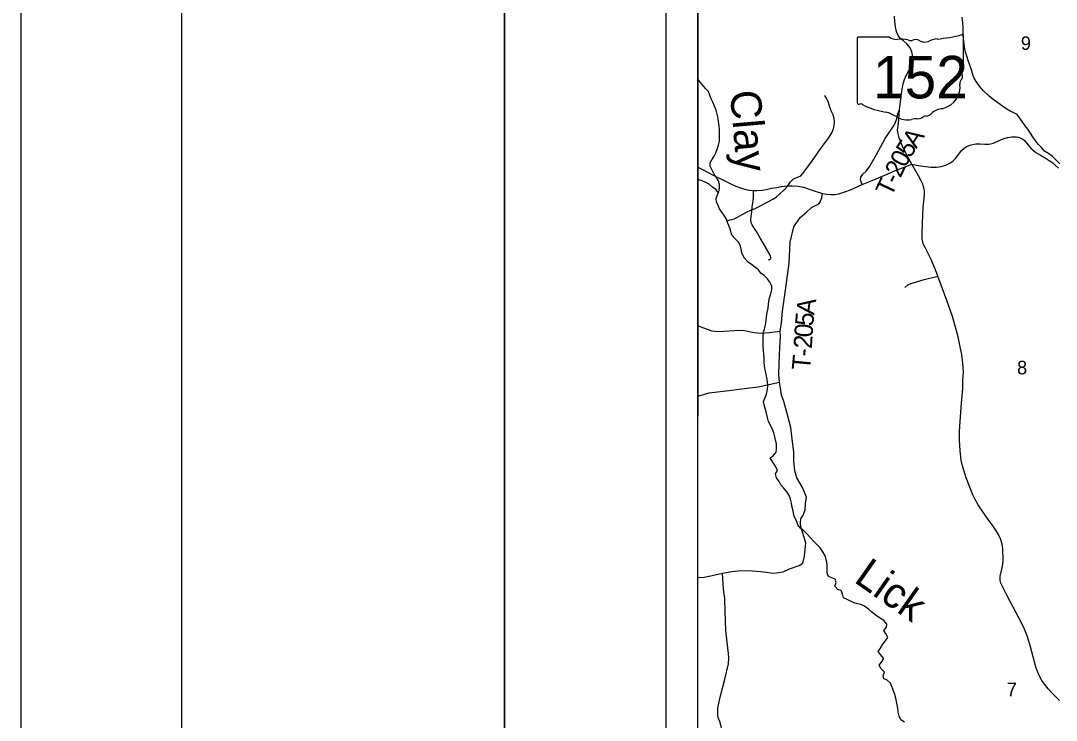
# Model space of a CAD drawing. Extents: x 0 to 34, y 0 to 22.
# Drawn here: x 0 to 3.211, y 16.097 to 18.266 of the extents above; entities that cross this region are included whole.
import ezdxf

# ---------------------------------------------------------------- set-up
doc = ezdxf.new("R2010")
doc.units = 0
for name, color, linetype in [('GM_X_Corporation', 7, 'Continuous'), ('GM_X_Minor_River', 7, 'Continuous'), ('GM_X_Minor_River_Text', 7, 'Continuous'), ('GM_X_Section_Text', 7, 'Continuous'), ('GM_X_State_Location', 7, 'Continuous'), ('GM_X_State_Route', 7, 'Continuous'), ('GM_X_State_Shield', 7, 'Continuous'), ('GM_X_Township_Road', 7, 'Continuous'), ('GM_X_Township_Road_Text', 7, 'Continuous'), ('SH_Border', 7, 'Continuous'), ('SH_Cut_Line', 7, 'Continuous'), ('SH_Data', 7, 'Continuous')]:
    doc.layers.add(name, color=color, linetype=linetype)

msp = doc.modelspace()

# ---------------------------------------------------------------- linework, layer by layer
at = {"layer": 'GM_X_Corporation'}
msp.add_lwpolyline([(4.6083, 17.0396), (4.6111, 17.2406), (4.6176, 17.7005), (4.6283, 18.459), (4.6386, 19.1863), (4.6534, 20.2382), (4.6627, 20.9), (2.1, 20.9), (2.1, 17.0396)], dxfattribs=at)
at = {"layer": 'GM_X_Minor_River'}
for points in [[(3.2225, 17.822), (3.2087, 17.8363), (3.1983, 17.8457), (3.1875, 17.8543), (3.1744, 17.8621), (3.1652, 17.8726), (3.1551, 17.8831), (3.1455, 17.8955), (3.1389, 17.9057), (3.1315, 17.9174), (3.1229, 17.9294), (3.1148, 17.94), (3.0978, 17.9641), (3.0896, 17.975), (3.0796, 17.9806), (3.0682, 17.9857), (3.0578, 17.9924), (3.0447, 18.0014), (3.0298, 18.0111), (3.0155, 18.0223), (3.0029, 18.0324), (2.9855, 18.0492), (2.9735, 18.0631), (2.9631, 18.0775), (2.9557, 18.0899), (2.9509, 18.1028), (2.9481, 18.1138), (2.939, 18.1399), (2.9335, 18.1562), (2.9299, 18.169), (2.927, 18.1846), (2.9241, 18.2032), (2.9228, 18.2195), (2.9224, 18.2454), (2.9215, 18.2598), (2.9197, 18.2769)], [(2.244, 17.5295), (2.2374, 17.5435), (2.2317, 17.5674), (2.2266, 17.5787), (2.2151, 17.5896), (2.2054, 17.6013), (2.1998, 17.6202), (2.1959, 17.6308), (2.1919, 17.6406), (2.1884, 17.6512), (2.1818, 17.6626), (2.1736, 17.6723), (2.167, 17.6833), (2.1623, 17.6935), (2.1572, 17.7048), (2.1563, 17.7151), (2.1611, 17.7265), (2.1652, 17.7361), (2.1673, 17.7456), (2.1664, 17.7586), (2.164, 17.7696), (2.1577, 17.7805), (2.1504, 17.7903), (2.1437, 17.8031), (2.1382, 17.8152), (2.1381, 17.8251), (2.1429, 17.8347), (2.1504, 17.8462), (2.156, 17.8569), (2.16, 17.8676), (2.1636, 17.8798), (2.1665, 17.8928), (2.1671, 17.9069), (2.1673, 17.9175), (2.1668, 17.9286), (2.1655, 17.9411), (2.1642, 17.9525), (2.1625, 17.9635), (2.1597, 17.9764), (2.1561, 17.9889), (2.151, 18.0014), (2.1459, 18.0135), (2.1412, 18.0237), (2.1368, 18.035), (2.1329, 18.0468), (2.1236, 18.0565), (2.1128, 18.0682), (2.1031, 18.0806), (2.1, 18.0867)], [(2.1902, 17.6457), (2.1998, 17.6491), (2.2127, 17.652), (2.2225, 17.6566), (2.2376, 17.6656), (2.2505, 17.6722), (2.2645, 17.6789), (2.2773, 17.684), (2.2902, 17.6903), (2.3012, 17.6965), (2.311, 17.702), (2.3212, 17.707), (2.3321, 17.7129), (2.3423, 17.7191), (2.3555, 17.7307), (2.366, 17.7404), (2.3784, 17.7546), (2.3855, 17.7653), (2.396, 17.7761), (2.4069, 17.7805), (2.4191, 17.7852), (2.4288, 17.7963), (2.437, 17.8075), (2.4467, 17.8213), (2.4561, 17.8347), (2.4643, 17.8466), (2.4729, 17.8589), (2.4916, 17.8843), (2.4998, 17.895), (2.5069, 17.905), (2.5155, 17.9181), (2.5206, 17.9307), (2.5224, 17.9414), (2.523, 17.952), (2.5221, 17.9627), (2.5189, 17.9744), (2.5134, 17.9869), (2.5075, 18.0016), (2.5047, 18.0122), (2.4996, 18.0244), (2.493, 18.0341)], [(2.1637, 17.7327), (2.1556, 17.7424), (2.1456, 17.7503), (2.1348, 17.7589), (2.1245, 17.7648), (2.1134, 17.7696), (2.1027, 17.7729), (2.1, 17.7735)], [(2.6292, 16.4421), (2.6169, 16.4511), (2.6051, 16.4566), (2.5948, 16.4584), (2.5844, 16.4616), (2.5733, 16.4668), (2.563, 16.472), (2.5515, 16.4764), (2.5479, 16.4893), (2.544, 16.4991), (2.5337, 16.5027), (2.5244, 16.5129), (2.5284, 16.5243), (2.5256, 16.535), (2.5153, 16.539), (2.5046, 16.5426), (2.501, 16.5532), (2.5005, 16.5665), (2.5011, 16.5764), (2.4998, 16.5874), (2.4942, 16.6071), (2.4876, 16.6196), (2.479, 16.6316), (2.469, 16.6418), (2.4586, 16.6523), (2.4486, 16.6632), (2.4389, 16.6744), (2.4285, 16.6846), (2.4185, 16.6924), (2.41, 16.7033), (2.4068, 16.7132), (2.4017, 16.723), (2.3978, 16.7336), (2.3949, 16.7464), (2.3925, 16.7571), (2.3901, 16.77), (2.3872, 16.7828), (2.3829, 16.7946), (2.3766, 16.8047), (2.3651, 16.8175), (2.3573, 16.8277), (2.3515, 16.8375), (2.3433, 16.8484), (2.3409, 16.8609), (2.3464, 16.872), (2.3414, 16.883), (2.332, 16.898), (2.3235, 16.9109), (2.3333, 16.9175), (2.3423, 16.9282), (2.3433, 16.9385), (2.3434, 16.9545), (2.341, 16.9658), (2.3382, 16.9765), (2.335, 16.9882), (2.3314, 16.9992), (2.3256, 17.0097), (2.3193, 17.0237), (2.3153, 17.0362), (2.3117, 17.0533), (2.3089, 17.0639), (2.3053, 17.0752), (2.3032, 17.0855), (2.308, 17.0977), (2.3128, 17.1084), (2.3161, 17.1225), (2.3163, 17.1358), (2.3149, 17.1541), (2.3112, 17.1708), (2.3088, 17.1836), (2.3063, 17.1958), (2.305, 17.2072), (2.3049, 17.2197), (2.304, 17.2315), (2.3034, 17.244), (2.3025, 17.2554), (2.3019, 17.2672), (2.3018, 17.2767), (2.3021, 17.2866), (2.3038, 17.3003), (2.3063, 17.3102), (2.31, 17.3232), (2.3117, 17.3373), (2.313, 17.348), (2.3148, 17.3617), (2.3173, 17.3746), (2.3186, 17.3864), (2.32, 17.3967), (2.3221, 17.4074), (2.3262, 17.4196), (2.3294, 17.4318), (2.3289, 17.4429), (2.3234, 17.4557), (2.3157, 17.4655), (2.3049, 17.4764), (2.2949, 17.4831), (2.2883, 17.4936), (2.2756, 17.5034), (2.2656, 17.5101), (2.2556, 17.5179), (2.244, 17.5295)], [(2.7401, 16.0912), (2.7294, 16.0983), (2.7239, 16.1096), (2.7214, 16.1221), (2.7194, 16.1343), (2.7181, 16.1453), (2.716, 16.1555), (2.7136, 16.1661), (2.7104, 16.1767), (2.7017, 16.2017), (2.6974, 16.2127), (2.6862, 16.2228), (2.6763, 16.2257), (2.6742, 16.2359), (2.6783, 16.2462), (2.6686, 16.2567), (2.6616, 16.2677), (2.6695, 16.2777), (2.6766, 16.2888), (2.6661, 16.3008), (2.6592, 16.311), (2.6662, 16.321), (2.6737, 16.3328), (2.6815, 16.3432), (2.689, 16.354), (2.6836, 16.3638), (2.6762, 16.3751), (2.6844, 16.3862), (2.6854, 16.3957), (2.6765, 16.4066), (2.6646, 16.4141), (2.6539, 16.4211), (2.6393, 16.4327), (2.6292, 16.4421)]]:
    msp.add_lwpolyline(points, dxfattribs=at)
at = {"layer": 'GM_X_State_Route'}
for points in [[(2.7636, 17.8211), (2.7507, 17.8433), (2.734, 17.8767), (2.7288, 17.89), (2.7241, 17.9028), (2.7204, 17.9157), (2.7189, 17.9263), (2.722, 17.9477), (2.7252, 17.9894), (2.7269, 18.0072), (2.7309, 18.0393), (2.7329, 18.0538), (2.7362, 18.0707), (2.7406, 18.0839), (2.7458, 18.0965), (2.7538, 18.1118), (2.76, 18.1247), (2.7631, 18.1364), (2.7652, 18.1509), (2.7649, 18.1605), (2.7634, 18.1692), (2.7609, 18.175), (2.7576, 18.182), (2.7485, 18.1938), (2.7375, 18.2037), (2.7286, 18.2108), (2.7223, 18.2178), (2.7166, 18.2292), (2.7133, 18.2396), (2.7104, 18.2638), (2.7096, 18.2803)], [(2.7636, 17.8211), (2.7766, 17.8183), (2.8057, 17.8139), (2.8226, 17.812), (2.8401, 17.8116), (2.8538, 17.814), (2.8685, 17.8188), (2.8807, 17.8244), (2.8909, 17.831), (2.8984, 17.8388), (2.9085, 17.8528), (2.9168, 17.8638), (2.9255, 17.8713), (2.9332, 17.8762), (2.9473, 17.881), (2.9615, 17.8843), (2.9756, 17.8849), (2.9896, 17.8838), (3.001, 17.8835), (3.0073, 17.8841), (3.0161, 17.8869), (3.0324, 17.894), (3.0414, 17.8978), (3.0493, 17.9005), (3.0611, 17.9037), (3.0729, 17.9058), (3.0816, 17.9062), (3.0883, 17.9058), (3.0943, 17.9046), (3.1011, 17.9021), (3.1074, 17.8987), (3.1123, 17.8944), (3.1168, 17.8892), (3.1323, 17.8714), (3.1396, 17.8645), (3.1478, 17.8579), (3.1622, 17.8491), (3.1795, 17.8387), (3.1893, 17.8331), (3.2003, 17.8254), (3.2091, 17.8174), (3.2179, 17.8086)], [(2.1, 17.8119), (2.1139, 17.8049), (2.1448, 17.7886), (2.1792, 17.7716), (2.2025, 17.7603), (2.2176, 17.7535), (2.2321, 17.748), (2.2447, 17.7442), (2.2601, 17.7409), (2.2722, 17.7397), (2.2831, 17.7396), (2.3001, 17.7409), (2.3113, 17.7431), (2.3285, 17.7466), (2.3443, 17.7495), (2.3595, 17.7521), (2.3773, 17.7539), (2.3924, 17.7546), (2.4107, 17.7534), (2.4271, 17.7497), (2.4454, 17.7442), (2.4639, 17.7379), (2.4862, 17.73)], [(2.6089, 17.7583), (2.625, 17.765), (2.6406, 17.7707), (2.6791, 17.7873), (2.7152, 17.8028), (2.7391, 17.8125), (2.7636, 17.8211)], [(3.0685, 16.4656), (3.0546, 16.4913), (3.045, 16.5101), (3.0393, 16.5226), (3.0374, 16.5309), (3.0368, 16.5445), (3.042, 16.5655), (3.0457, 16.5814), (3.0467, 16.595), (3.0451, 16.6283), (3.0433, 16.6434), (3.0382, 16.6599), (3.0317, 16.6735), (3.0239, 16.6864), (3.0186, 16.6937), (3.0129, 16.7025), (3.0022, 16.7171), (2.9867, 16.7391), (2.9692, 16.765), (2.96, 16.7815), (2.9525, 16.7966), (2.9315, 16.8494), (2.9203, 16.8866), (2.9163, 16.9038), (2.9127, 16.9323), (2.9109, 16.9668), (2.9106, 16.9922), (2.9129, 17.0234), (2.9177, 17.0799), (2.9209, 17.126), (2.9215, 17.1513), (2.9236, 17.1766), (2.9218, 17.2045), (2.918, 17.2318), (2.9127, 17.2551), (2.9071, 17.2862), (2.9007, 17.3089), (2.8889, 17.3495), (2.8719, 17.3992), (2.8547, 17.4462), (2.8437, 17.4743), (2.837, 17.4937), (2.8275, 17.5158), (2.8229, 17.5255), (2.8177, 17.5365), (2.8114, 17.5489), (2.8052, 17.5607), (2.7993, 17.5727), (2.7966, 17.5822), (2.795, 17.592), (2.7948, 17.6053), (2.7964, 17.638), (2.7988, 17.6867), (2.8021, 17.7268), (2.8021, 17.739), (2.8008, 17.748), (2.7985, 17.7557), (2.7969, 17.7597), (2.7921, 17.7697), (2.7836, 17.7852), (2.7636, 17.8211)], [(2.4862, 17.73), (2.4985, 17.7281), (2.5118, 17.7271), (2.5244, 17.7276), (2.5372, 17.7297), (2.555, 17.7352), (2.5728, 17.742), (2.6089, 17.7583)], [(3.2208, 16.1586), (3.1981, 16.1808), (3.1864, 16.195), (3.1762, 16.2078), (3.1666, 16.221), (3.1577, 16.2362), (3.1489, 16.2589), (3.1395, 16.294), (3.1311, 16.3249), (3.1261, 16.3421), (3.1206, 16.3586), (3.113, 16.3801), (3.1039, 16.3976), (3.0767, 16.4505), (3.0685, 16.4656)]]:
    msp.add_lwpolyline(points, dxfattribs=at)
at = {"layer": 'GM_X_State_Shield'}
for p, q in [((2.5938, 18.2114), (2.5938, 18.0112)), ((2.6936, 18.2148), (2.5971, 18.2148)), ((2.9234, 18.1151), (2.9234, 18.2198)), ((2.9234, 18.1151), (2.9234, 18.1151))]:
    msp.add_line(p, q, dxfattribs=at)
for centre, major_axis, start_param, end_param in [((2.5976, 18.2118), (0.00382, 0), 1.712693, 3.28349), ((2.7166, 18.238), (0.037, 0), 4.042523, 4.731795), ((2.7289, 18.1024), (0.133, 0), 1.404758, 1.657858), ((2.7747, 18.1897), (0.0222, 0), 0.950623, 2.079405), ((2.8506, 18.1537), (0.0703, 0), 1.699011, 2.107814), ((2.806, 18.4876), (0.3495, 0), 4.814394, 5.042369), ((2.9198, 18.2202), (0.00367, 0), 6.141152, 7.989035), ((2.7591, 18.2128), (0.0107, 0), 3.836095, 5.185415), ((2.8034, 18.2214), (0.0267, 0), 4.081561, 5.145723), ((2.9226, 18.1074), (0.00568, 0), 1.883978, 3.671073), ((2.9195, 18.1147), (0.00393, 0), 5.05454, 6.418171), ((2.9366, 18.0713), (0.0248, 0), 2.387724, 3.262537), ((2.8865, 18.0942), (0.0341, 0), 5.934695, 6.695948), ((2.8256, 18.0579), (0.0874, 0), 5.101752, 6.440018), ((2.5976, 18.0108), (0.00385, 0), 3.00124, 4.508301), ((2.5982, 18.0313), (0.0294, 0), 4.665946, 4.897461), ((2.6042, 17.9997), (0.0106, 0), 0.519207, 1.627899), ((2.7381, 18.1795), (0.2524, 0), 4.195997, 4.488961), ((2.8625, 17.9551), (0.0479, 0), 1.647645, 2.488434), ((2.6628, 17.9213), (0.079, 0), 0.823519, 1.323587), ((2.7482, 17.9987), (0.0501, 0), 4.026481, 4.996735), ((2.7772, 17.9295), (0.0412, 0), 1.495662, 1.94098), ((2.7809, 17.9837), (0.0267, 0), 4.691044, 5.507374), ((2.805, 17.9643), (0.00752, 0), 1.147584, 2.315152), ((2.8018, 17.9918), (0.0282, 0), 4.937069, 5.64225)]:
    msp.add_ellipse(centre, major_axis=major_axis, ratio=0.8, start_param=start_param, end_param=end_param, dxfattribs=at)
at = {"layer": 'GM_X_Township_Road'}
for points in [[(2.6089, 17.7583), (2.6042, 17.7718), (2.6052, 17.7814), (2.6117, 17.7906), (2.6217, 17.8002), (2.6333, 17.8152), (2.6541, 17.8514), (2.6804, 17.9014), (2.7083, 17.942), (2.7131, 17.9512), (2.7164, 17.9622), (2.7184, 17.9726), (2.7216, 17.9834), (2.7252, 17.9894)], [(2.4862, 17.73), (2.4985, 17.7281), (2.5118, 17.7271), (2.5244, 17.7276), (2.5372, 17.7297), (2.555, 17.7352), (2.5728, 17.742), (2.6089, 17.7583)], [(2.3186, 17.5249), (2.3207, 17.5256), (2.3231, 17.5262), (2.3246, 17.5278), (2.3258, 17.5297), (2.3262, 17.5321), (2.3253, 17.5358), (2.3228, 17.5412), (2.3122, 17.5591), (2.294, 17.5914), (2.2811, 17.6127), (2.2771, 17.619), (2.2732, 17.6254), (2.2686, 17.633), (2.2665, 17.6373), (2.265, 17.6417), (2.2644, 17.645), (2.2641, 17.6498), (2.2647, 17.6576), (2.2667, 17.6744), (2.2686, 17.6897), (2.2702, 17.7002), (2.271, 17.7083), (2.2719, 17.7159), (2.2723, 17.7249), (2.2722, 17.7397)], [(2.3528, 17.146), (2.3507, 17.1679), (2.3518, 17.204), (2.3544, 17.2534), (2.3558, 17.2876), (2.3551, 17.3034), (2.3592, 17.3292), (2.362, 17.3655), (2.3715, 17.4312), (2.3833, 17.5146), (2.3857, 17.5792), (2.3972, 17.6273), (2.4174, 17.6558), (2.4364, 17.6729), (2.4521, 17.6869), (2.4603, 17.6909), (2.4744, 17.6982), (2.4786, 17.7049), (2.484, 17.7169), (2.4862, 17.73)], [(2.7417, 17.4392), (2.7504, 17.4474), (2.7647, 17.4528), (2.8013, 17.4637), (2.8437, 17.4743)], [(2.1, 17.3217), (2.1141, 17.3149), (2.1291, 17.3098), (2.1436, 17.3048), (2.1642, 17.3023), (2.2292, 17.3069), (2.2444, 17.3058), (2.2746, 17.2997), (2.2953, 17.2976), (2.3205, 17.2995), (2.3551, 17.3034)], [(2.1, 17.1024), (2.1348, 17.1128), (2.2039, 17.1207)], [(2.1765, 16.5529), (2.2055, 16.5581), (2.2353, 16.5615), (2.2685, 16.5601), (2.2953, 16.5587), (2.3349, 16.5532), (2.3648, 16.5575), (2.3838, 16.5664), (2.4139, 16.5776), (2.4251, 16.5843), (2.4302, 16.6062), (2.4327, 16.6275), (2.4343, 16.6464), (2.4307, 16.6606), (2.4231, 16.6836), (2.419, 16.6963), (2.418, 16.709), (2.4188, 16.7214), (2.4258, 16.7329), (2.4322, 16.7501), (2.4337, 16.7695), (2.4368, 16.789), (2.4246, 16.8185), (2.4068, 16.8491), (2.4001, 16.871), (2.3976, 16.9005), (2.3971, 16.9295), (2.3925, 16.9693), (2.3879, 17.0054), (2.3777, 17.0446), (2.366, 17.0859), (2.3594, 17.1052), (2.3558, 17.1266), (2.3528, 17.146)], [(2.2039, 17.1207), (2.2449, 17.1254), (2.2863, 17.1314), (2.3528, 17.146)], [(2.1, 16.5414), (2.103, 16.5404), (2.1195, 16.5412), (2.135, 16.544), (2.1765, 16.5529)], [(2.2547, 15.9306), (2.2109, 15.9927), (2.2009, 16.0061), (2.1892, 16.0253), (2.1777, 16.0582), (2.1677, 16.0933), (2.163, 16.1054), (2.1612, 16.1152), (2.1612, 16.1267), (2.1621, 16.1357), (2.1695, 16.1735), (2.1833, 16.2247), (2.1943, 16.2722), (2.1958, 16.2895), (2.195, 16.3043), (2.1869, 16.3755), (2.1842, 16.4343), (2.1837, 16.4743), (2.1793, 16.5039), (2.1765, 16.5529)]]:
    msp.add_lwpolyline(points, dxfattribs=at)
at = {"layer": 'SH_Border'}
for points in [[(0.5, 21.5), (1.5, 21.5), (1.5, 0.5), (0.5, 0.5)], [(1.5, 21.5), (33.5, 21.5), (33.5, 0.5), (1.5, 0.5)]]:
    msp.add_lwpolyline(points, close=True, dxfattribs=at)
at = {"layer": 'SH_Cut_Line'}
msp.add_lwpolyline([(0, 0), (34, 0), (34, 22), (0, 22)], close=True, dxfattribs=at)
at = {"layer": 'SH_Data'}
msp.add_line((2, 21), (2, 14), dxfattribs=at)
msp.add_lwpolyline([(2.1, 20.9), (8.9, 20.9), (8.9, 14.1), (2.1, 14.1)], close=True, dxfattribs=at)

# ---------------------------------------------------------------- texts
at = {"layer": 'GM_X_Minor_River_Text'}
for s, height, rotation, p in [('Clay', 0.09471, 274.9646, (2.1991, 18.0473)), ('Lick', 0.0947, 324.9731, (2.5804, 16.528))]:
    msp.add_text(s, height=height, rotation=rotation, dxfattribs=at).set_placement(p)
at = {"layer": 'GM_X_Section_Text'}
for s, p in [('9', (3.1014, 18.1757)), ('8', (3.0897, 17.1698)), ('7', (3.0577, 16.172))]:
    msp.add_text(s, height=0.0419, rotation=0, dxfattribs=at).set_placement(p)
at = {"layer": 'GM_X_State_Location'}
msp.add_text('152', height=0.000189, rotation=0, dxfattribs=at).set_placement((2.6881, 18.0842))
for s in ['s', 'r']:
    msp.add_text(s, height=0.000189, dxfattribs=at).set_placement((2.7549, 18.098))
at = {"layer": 'GM_X_State_Shield'}
msp.add_text('152', height=0.13184, dxfattribs=at).set_placement((2.6428, 18.0253))
at = {"layer": 'GM_X_Township_Road_Text'}
for s, rotation, p in [('A', 56.3221, (2.7768, 17.8674)), ('5', 58.2892, (2.7587, 17.8381)), ('0', 62.3108, (2.743, 17.808)), ('2', 64.1773, (2.7279, 17.7769)), ('T', 64.6885, (2.6998, 17.7176)), ('-', 64.594, (2.718, 17.756)), ('A', 82.4005, (2.4603, 17.352)), ('5', 84.9351, (2.4572, 17.3178)), ('0', 86.7037, (2.4553, 17.2833)), ('2', 86.4391, (2.4531, 17.2481)), ('-', 85.367, (2.4511, 17.2237)), ('T', 84.8071, (2.4472, 17.1807))]:
    msp.add_text(s, height=0.0568, rotation=rotation, dxfattribs=at).set_placement(p)

doc.saveas('drawing.dxf')
